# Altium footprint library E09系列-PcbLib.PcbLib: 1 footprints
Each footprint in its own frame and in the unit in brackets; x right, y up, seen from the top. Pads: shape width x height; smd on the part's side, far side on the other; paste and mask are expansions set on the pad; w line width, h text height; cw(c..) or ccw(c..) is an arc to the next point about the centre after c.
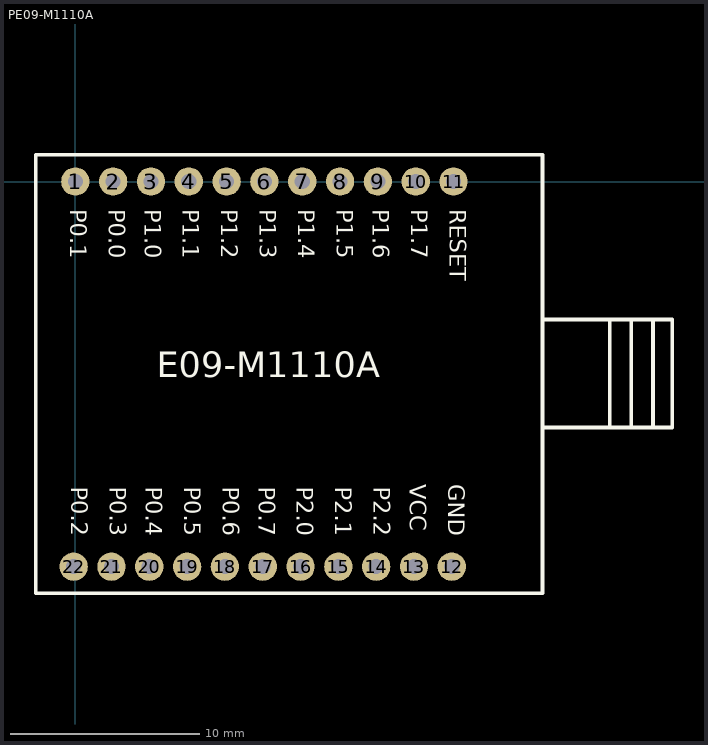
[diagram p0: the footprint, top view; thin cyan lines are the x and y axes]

## PE09-M1110A [mm] "26.9mm*23.4mm-D"
pads (22):
  round 1.5 hole 0.8: 1(0,0) 2(2,0) 3(4,0) 4(6,0) 5(8,0) 6(10,0) 7(12,0) 8(14,0) 9(16,0) 10(18,0) 11(20,0) 12(19.91,-20.368) 13(17.91,-20.368) 14(15.91,-20.368) 15(13.91,-20.368) 16(11.91,-20.368) 17(9.91,-20.368) 18(7.91,-20.368) 19(5.91,-20.368) 20(3.91,-20.368) 21(1.91,-20.368) 22(-0.09,-20.368)
Top Overlay:
  lines w0.2: 24.707,-13.011 30.549,-13.011 30.549,-7.296 ; 24.71,-7.296 31.565,-7.296 31.565,-13.011 30.295,-13.011 ; 28.263,-13.011 28.263,-7.296 ; 29.406,-13.011 29.406,-7.296 ; -2.09,-21.774 24.71,-21.774 24.71,1.416 -2.09,1.416 -2.09,-21.774
  text "P0.2" at -0.508,-16.129 h1.5
  text "P0.4" at 3.429,-16.129 h1.5
  text "P0.5" at 5.461,-16.129 h1.5
  text "P0.7" at 9.398,-16.129 h1.5
  text "P2.2" at 15.494,-16.129 h1.5
  text "VCC" at 17.399,-16.002 h1.5
  text "E09-M1110A" at 4.318,-10.795 h2.3
  text "P1.7" at 17.468,-1.454 h1.5
  text "P1.5" at 13.531,-1.454 h1.5
  text "P1.3" at 9.467,-1.454 h1.5
  text "P1.0" at 3.371,-1.454 h1.5
  text "P0.0" at 1.466,-1.454 h1.5
  text "P0.1" at -0.566,-1.454 h1.5
  text "P1.1" at 5.403,-1.454 h1.5
  text "P1.2" at 7.435,-1.454 h1.5
  text "P1.4" at 11.499,-1.454 h1.5
  text "P1.6" at 15.436,-1.454 h1.5
  text "RESET" at 19.5,-1.454 h1.5
  text "GND" at 19.431,-16.002 h1.5
  text "P2.1" at 13.462,-16.129 h1.5
  text "P2.0" at 11.43,-16.129 h1.5
  text "P0.6" at 7.493,-16.129 h1.5
  text "P0.3" at 1.524,-16.129 h1.5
